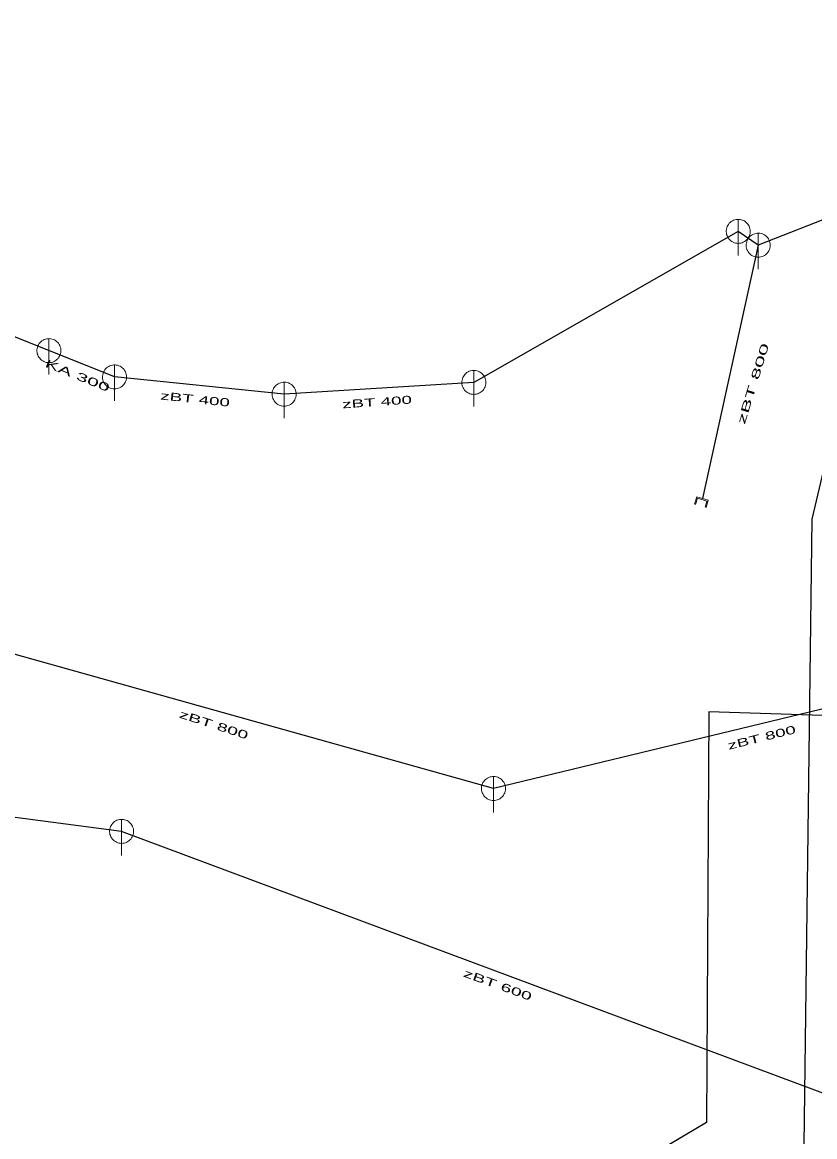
# Model space of a CAD drawing. Extents: x -688432 to -687974, y -973332 to -972704.
# Drawn here: x -688214.9 to -688148.9, y -972930.3 to -972837.5 of the extents above; entities that cross this region are included whole.
import ezdxf
from ezdxf.enums import TextEntityAlignment as Align

# ---------------------------------------------------------------- set-up
doc = ezdxf.new("R2010")
doc.units = 0
doc.header["$LTSCALE"] = 0.27
for name, color, linetype, lineweight in [('1', 7, 'Continuous', 25), ('14', 7, 'Continuous', 25), ('17', 7, 'Continuous', 25), ('22', 7, 'Continuous', 13), ('29', 7, 'Continuous', 13)]:
    doc.layers.add(name, color=color, linetype=linetype, lineweight=lineweight)

msp = doc.modelspace()

# ---------------------------------------------------------------- linework, layer by layer
at = {"layer": '1'}
msp.add_lwpolyline([(-688157.895, -972985.064), (-688131.748, -972983.489), (-688134.952, -972934.372), (-688122, -972934.52), (-688122.986, -972921.456), (-688135.938, -972921.308), (-688137.958, -972895.554), (-688157.714, -972894.909), (-688157.93, -972929.126), (-688173.215, -972938.189), (-688162.29, -972954.057)], close=True, dxfattribs=at)
at = {"layer": '14'}
for p, q in [((-688146.3, -972853.175), (-688153.616, -972856.054)), ((-688155.276, -972854.901), (-688177.28, -972867.48)), ((-688153.616, -972856.054), (-688155.276, -972854.901)), ((-688153.616, -972856.054), (-688158.259, -972877.162)), ((-688193.074, -972868.464), (-688207.188, -972867.028)), ((-688177.28, -972867.48), (-688193.074, -972868.464)), ((-688175.649, -972901.305), (-688217.084, -972889.702)), ((-688131.138, -972890.529), (-688175.649, -972901.305)), ((-688206.6, -972904.874), (-688245.539, -972899.801)), ((-688142.939, -972928.669), (-688206.6, -972904.874))]:
    msp.add_line(p, q, dxfattribs=at)
msp.add_lwpolyline([(-688207.188, -972867.028), (-688212.648, -972864.838), (-688224.272, -972860.177)], dxfattribs=at)
at = {"layer": '17'}
msp.add_lwpolyline([(-688123.609, -972815.609), (-688135.91, -972839.761), (-688146.524, -972867.704), (-688149.164, -972878.87), (-688150.368, -972974.473), (-688134.778, -973051.136), (-688125.903, -973068.701), (-688203.651, -973132.27), (-688148.612, -973199.748), (-688078.631, -973291.807), (-688049.631, -973331.642)], dxfattribs=at)
at = {"layer": '22'}
for p, q in [((-688155.276, -972856.901), (-688155.275, -972853.901)), ((-688153.616, -972858.054), (-688153.615, -972855.054)), ((-688212.648, -972866.838), (-688212.647, -972863.838)), ((-688207.188, -972869.028), (-688207.187, -972866.028)), ((-688177.28, -972869.48), (-688177.279, -972866.48)), ((-688193.074, -972870.464), (-688193.073, -972867.464)), ((-688175.65, -972903.305), (-688175.649, -972900.305)), ((-688206.6, -972906.874), (-688206.599, -972903.874))]:
    msp.add_line(p, q, dxfattribs=at)
for points in [[(-688154.276, -972854.901), (-688154.281, -972854.792), (-688154.299, -972854.684), (-688154.329, -972854.578), (-688154.369, -972854.477), (-688154.421, -972854.38), (-688154.483, -972854.29), (-688154.555, -972854.207), (-688154.635, -972854.133), (-688154.723, -972854.067), (-688154.817, -972854.012), (-688154.917, -972853.967), (-688155.022, -972853.934), (-688155.129, -972853.912), (-688155.238, -972853.902), (-688155.348, -972853.904), (-688155.456, -972853.918), (-688155.563, -972853.943), (-688155.666, -972853.98), (-688155.764, -972854.029), (-688155.856, -972854.087), (-688155.942, -972854.156), (-688156.019, -972854.233), (-688156.088, -972854.319), (-688156.147, -972854.411), (-688156.195, -972854.509), (-688156.232, -972854.612), (-688156.258, -972854.719), (-688156.272, -972854.827), (-688156.275, -972854.937), (-688156.265, -972855.046), (-688156.244, -972855.153), (-688156.21, -972855.257), (-688156.166, -972855.357), (-688156.111, -972855.452), (-688156.045, -972855.54), (-688155.971, -972855.62), (-688155.888, -972855.692), (-688155.798, -972855.754), (-688155.702, -972855.806), (-688155.6, -972855.847), (-688155.495, -972855.877), (-688155.387, -972855.895), (-688155.277, -972855.901), (-688155.168, -972855.895), (-688155.06, -972855.877), (-688154.955, -972855.848), (-688154.853, -972855.807), (-688154.756, -972855.755), (-688154.666, -972855.693), (-688154.583, -972855.622), (-688154.508, -972855.542), (-688154.443, -972855.454), (-688154.387, -972855.36), (-688154.343, -972855.26), (-688154.309, -972855.156), (-688154.287, -972855.048), (-688154.277, -972854.939)], [(-688152.616, -972856.054), (-688152.621, -972855.945), (-688152.639, -972855.837), (-688152.669, -972855.731), (-688152.709, -972855.63), (-688152.761, -972855.533), (-688152.823, -972855.443), (-688152.895, -972855.36), (-688152.975, -972855.286), (-688153.063, -972855.22), (-688153.157, -972855.165), (-688153.257, -972855.12), (-688153.362, -972855.087), (-688153.469, -972855.065), (-688153.578, -972855.055), (-688153.688, -972855.057), (-688153.796, -972855.071), (-688153.903, -972855.096), (-688154.006, -972855.133), (-688154.104, -972855.182), (-688154.196, -972855.24), (-688154.282, -972855.309), (-688154.359, -972855.386), (-688154.428, -972855.472), (-688154.487, -972855.564), (-688154.535, -972855.662), (-688154.572, -972855.765), (-688154.598, -972855.872), (-688154.612, -972855.98), (-688154.615, -972856.09), (-688154.605, -972856.199), (-688154.584, -972856.306), (-688154.55, -972856.41), (-688154.506, -972856.51), (-688154.451, -972856.605), (-688154.385, -972856.693), (-688154.311, -972856.773), (-688154.228, -972856.845), (-688154.138, -972856.907), (-688154.042, -972856.959), (-688153.94, -972857), (-688153.835, -972857.03), (-688153.727, -972857.048), (-688153.617, -972857.054), (-688153.508, -972857.048), (-688153.4, -972857.03), (-688153.295, -972857.001), (-688153.193, -972856.96), (-688153.096, -972856.908), (-688153.006, -972856.846), (-688152.923, -972856.775), (-688152.848, -972856.695), (-688152.783, -972856.607), (-688152.727, -972856.513), (-688152.683, -972856.413), (-688152.649, -972856.309), (-688152.627, -972856.201), (-688152.617, -972856.092)], [(-688211.648, -972864.838), (-688211.653, -972864.729), (-688211.671, -972864.621), (-688211.701, -972864.515), (-688211.741, -972864.414), (-688211.793, -972864.317), (-688211.855, -972864.227), (-688211.927, -972864.144), (-688212.007, -972864.07), (-688212.095, -972864.004), (-688212.189, -972863.949), (-688212.289, -972863.904), (-688212.394, -972863.871), (-688212.501, -972863.849), (-688212.61, -972863.839), (-688212.72, -972863.841), (-688212.828, -972863.855), (-688212.935, -972863.88), (-688213.038, -972863.917), (-688213.136, -972863.966), (-688213.228, -972864.024), (-688213.314, -972864.093), (-688213.391, -972864.17), (-688213.46, -972864.256), (-688213.519, -972864.348), (-688213.567, -972864.446), (-688213.604, -972864.549), (-688213.63, -972864.656), (-688213.644, -972864.764), (-688213.647, -972864.874), (-688213.637, -972864.983), (-688213.616, -972865.09), (-688213.582, -972865.194), (-688213.538, -972865.294), (-688213.483, -972865.389), (-688213.417, -972865.477), (-688213.343, -972865.557), (-688213.26, -972865.629), (-688213.17, -972865.691), (-688213.074, -972865.743), (-688212.972, -972865.784), (-688212.867, -972865.814), (-688212.759, -972865.832), (-688212.649, -972865.838), (-688212.54, -972865.832), (-688212.432, -972865.814), (-688212.327, -972865.785), (-688212.225, -972865.744), (-688212.128, -972865.692), (-688212.038, -972865.63), (-688211.955, -972865.559), (-688211.88, -972865.479), (-688211.815, -972865.391), (-688211.759, -972865.297), (-688211.715, -972865.197), (-688211.681, -972865.093), (-688211.659, -972864.985), (-688211.649, -972864.876)], [(-688206.188, -972867.028), (-688206.193, -972866.919), (-688206.211, -972866.811), (-688206.241, -972866.705), (-688206.281, -972866.604), (-688206.333, -972866.507), (-688206.395, -972866.417), (-688206.467, -972866.334), (-688206.547, -972866.26), (-688206.635, -972866.194), (-688206.729, -972866.139), (-688206.829, -972866.094), (-688206.934, -972866.061), (-688207.041, -972866.039), (-688207.15, -972866.029), (-688207.26, -972866.031), (-688207.368, -972866.045), (-688207.475, -972866.07), (-688207.578, -972866.107), (-688207.676, -972866.156), (-688207.768, -972866.214), (-688207.854, -972866.283), (-688207.931, -972866.36), (-688208, -972866.446), (-688208.059, -972866.538), (-688208.107, -972866.636), (-688208.144, -972866.739), (-688208.17, -972866.846), (-688208.184, -972866.954), (-688208.187, -972867.064), (-688208.177, -972867.173), (-688208.156, -972867.28), (-688208.122, -972867.384), (-688208.078, -972867.484), (-688208.023, -972867.579), (-688207.957, -972867.667), (-688207.883, -972867.747), (-688207.8, -972867.819), (-688207.71, -972867.881), (-688207.614, -972867.933), (-688207.512, -972867.974), (-688207.407, -972868.004), (-688207.299, -972868.022), (-688207.189, -972868.028), (-688207.08, -972868.022), (-688206.972, -972868.004), (-688206.867, -972867.975), (-688206.765, -972867.934), (-688206.668, -972867.882), (-688206.578, -972867.82), (-688206.495, -972867.749), (-688206.42, -972867.669), (-688206.355, -972867.581), (-688206.299, -972867.487), (-688206.255, -972867.387), (-688206.221, -972867.283), (-688206.199, -972867.175), (-688206.189, -972867.066)], [(-688176.28, -972867.48), (-688176.285, -972867.371), (-688176.303, -972867.263), (-688176.333, -972867.157), (-688176.373, -972867.056), (-688176.425, -972866.959), (-688176.487, -972866.869), (-688176.559, -972866.786), (-688176.639, -972866.712), (-688176.727, -972866.646), (-688176.821, -972866.591), (-688176.921, -972866.546), (-688177.026, -972866.513), (-688177.133, -972866.491), (-688177.242, -972866.481), (-688177.352, -972866.483), (-688177.46, -972866.497), (-688177.567, -972866.522), (-688177.67, -972866.559), (-688177.768, -972866.608), (-688177.86, -972866.666), (-688177.946, -972866.735), (-688178.023, -972866.812), (-688178.092, -972866.898), (-688178.151, -972866.99), (-688178.199, -972867.088), (-688178.236, -972867.191), (-688178.262, -972867.298), (-688178.276, -972867.406), (-688178.279, -972867.516), (-688178.269, -972867.625), (-688178.248, -972867.732), (-688178.214, -972867.836), (-688178.17, -972867.936), (-688178.115, -972868.031), (-688178.049, -972868.119), (-688177.975, -972868.199), (-688177.892, -972868.271), (-688177.802, -972868.333), (-688177.706, -972868.385), (-688177.604, -972868.426), (-688177.499, -972868.456), (-688177.391, -972868.474), (-688177.281, -972868.48), (-688177.172, -972868.474), (-688177.064, -972868.456), (-688176.959, -972868.427), (-688176.857, -972868.386), (-688176.76, -972868.334), (-688176.67, -972868.272), (-688176.587, -972868.201), (-688176.512, -972868.121), (-688176.447, -972868.033), (-688176.391, -972867.939), (-688176.347, -972867.839), (-688176.313, -972867.735), (-688176.291, -972867.627), (-688176.281, -972867.518)], [(-688192.074, -972868.464), (-688192.079, -972868.355), (-688192.097, -972868.247), (-688192.127, -972868.141), (-688192.167, -972868.04), (-688192.219, -972867.943), (-688192.281, -972867.853), (-688192.353, -972867.77), (-688192.433, -972867.696), (-688192.521, -972867.63), (-688192.615, -972867.575), (-688192.715, -972867.53), (-688192.82, -972867.497), (-688192.927, -972867.475), (-688193.036, -972867.465), (-688193.146, -972867.467), (-688193.254, -972867.481), (-688193.361, -972867.506), (-688193.464, -972867.543), (-688193.562, -972867.592), (-688193.654, -972867.65), (-688193.74, -972867.719), (-688193.817, -972867.796), (-688193.886, -972867.882), (-688193.945, -972867.974), (-688193.993, -972868.072), (-688194.03, -972868.175), (-688194.056, -972868.282), (-688194.07, -972868.39), (-688194.073, -972868.5), (-688194.063, -972868.609), (-688194.042, -972868.716), (-688194.008, -972868.82), (-688193.964, -972868.92), (-688193.909, -972869.015), (-688193.843, -972869.103), (-688193.769, -972869.183), (-688193.686, -972869.255), (-688193.596, -972869.317), (-688193.5, -972869.369), (-688193.398, -972869.41), (-688193.293, -972869.44), (-688193.185, -972869.458), (-688193.075, -972869.464), (-688192.966, -972869.458), (-688192.858, -972869.44), (-688192.753, -972869.411), (-688192.651, -972869.37), (-688192.554, -972869.318), (-688192.464, -972869.256), (-688192.381, -972869.185), (-688192.306, -972869.105), (-688192.241, -972869.017), (-688192.185, -972868.923), (-688192.141, -972868.823), (-688192.107, -972868.719), (-688192.085, -972868.611), (-688192.075, -972868.502)], [(-688174.65, -972901.305), (-688174.655, -972901.196), (-688174.673, -972901.088), (-688174.703, -972900.982), (-688174.743, -972900.881), (-688174.795, -972900.784), (-688174.857, -972900.694), (-688174.929, -972900.611), (-688175.009, -972900.537), (-688175.097, -972900.471), (-688175.191, -972900.416), (-688175.291, -972900.371), (-688175.396, -972900.338), (-688175.503, -972900.316), (-688175.612, -972900.306), (-688175.722, -972900.308), (-688175.83, -972900.322), (-688175.937, -972900.347), (-688176.04, -972900.384), (-688176.138, -972900.433), (-688176.23, -972900.491), (-688176.316, -972900.56), (-688176.393, -972900.637), (-688176.462, -972900.723), (-688176.521, -972900.815), (-688176.569, -972900.913), (-688176.606, -972901.016), (-688176.632, -972901.123), (-688176.646, -972901.231), (-688176.649, -972901.341), (-688176.639, -972901.45), (-688176.618, -972901.557), (-688176.584, -972901.661), (-688176.54, -972901.761), (-688176.485, -972901.856), (-688176.419, -972901.944), (-688176.345, -972902.024), (-688176.262, -972902.096), (-688176.172, -972902.158), (-688176.076, -972902.21), (-688175.974, -972902.251), (-688175.869, -972902.281), (-688175.761, -972902.299), (-688175.651, -972902.305), (-688175.542, -972902.299), (-688175.434, -972902.281), (-688175.329, -972902.252), (-688175.227, -972902.211), (-688175.13, -972902.159), (-688175.04, -972902.097), (-688174.957, -972902.026), (-688174.882, -972901.946), (-688174.817, -972901.858), (-688174.761, -972901.764), (-688174.717, -972901.664), (-688174.683, -972901.56), (-688174.661, -972901.452), (-688174.651, -972901.343)], [(-688205.6, -972904.874), (-688205.605, -972904.765), (-688205.623, -972904.657), (-688205.653, -972904.551), (-688205.693, -972904.45), (-688205.745, -972904.353), (-688205.807, -972904.263), (-688205.879, -972904.18), (-688205.959, -972904.106), (-688206.047, -972904.04), (-688206.141, -972903.985), (-688206.241, -972903.94), (-688206.346, -972903.907), (-688206.453, -972903.885), (-688206.562, -972903.875), (-688206.672, -972903.877), (-688206.78, -972903.891), (-688206.887, -972903.916), (-688206.99, -972903.953), (-688207.088, -972904.002), (-688207.18, -972904.06), (-688207.266, -972904.129), (-688207.343, -972904.206), (-688207.412, -972904.292), (-688207.471, -972904.384), (-688207.519, -972904.482), (-688207.556, -972904.585), (-688207.582, -972904.692), (-688207.596, -972904.8), (-688207.599, -972904.91), (-688207.589, -972905.019), (-688207.568, -972905.126), (-688207.534, -972905.23), (-688207.49, -972905.33), (-688207.435, -972905.425), (-688207.369, -972905.513), (-688207.295, -972905.593), (-688207.212, -972905.665), (-688207.122, -972905.727), (-688207.026, -972905.779), (-688206.924, -972905.82), (-688206.819, -972905.85), (-688206.711, -972905.868), (-688206.601, -972905.874), (-688206.492, -972905.868), (-688206.384, -972905.85), (-688206.279, -972905.821), (-688206.177, -972905.78), (-688206.08, -972905.728), (-688205.99, -972905.666), (-688205.907, -972905.595), (-688205.832, -972905.515), (-688205.767, -972905.427), (-688205.711, -972905.333), (-688205.667, -972905.233), (-688205.633, -972905.129), (-688205.611, -972905.021), (-688205.601, -972904.912)]]:
    msp.add_lwpolyline(points, close=True, dxfattribs=at)
at = {"layer": '29'}
for points in [[(-688157.957, -972877.898), (-688157.783, -972877.302), (-688158.734, -972877.022), (-688158.91, -972877.62)], [(-688158.826, -972877.644), (-688158.676, -972877.13), (-688157.891, -972877.361), (-688158.042, -972877.874)]]:
    msp.add_lwpolyline(points, dxfattribs=at)

# ---------------------------------------------------------------- texts
at = {"layer": '1'}
for s, rotation, width, p in [('zBT 800 ', 73, 2.1, (-688153.6453, -972867.4375)), ('zBT 800 ', 73, 2.1, (-688153.6453, -972867.4375)), ('zBT 800 ', 73, 2.1, (-688153.6453, -972867.4375)), ('zBT 800 ', 73, 2.1, (-688153.6453, -972867.4375)), ('zBT 800 ', 73, 2.1, (-688153.6453, -972867.4375)), ('KA 300', 338, 1.95, (-688210.3989, -972867.2224)), ('KA 300', 338, 1.95, (-688210.3989, -972867.2224)), ('KA 300', 338, 1.95, (-688210.3989, -972867.2224)), ('KA 300', 338, 1.95, (-688210.3989, -972867.2224)), ('KA 300', 338, 1.95, (-688210.3989, -972867.2224)), ('zBT 400 ', 354, 1.75, (-688200.2988, -972869.2256)), ('zBT 400 ', 354, 1.75, (-688200.2988, -972869.2256)), ('zBT 400 ', 354, 1.75, (-688200.2988, -972869.2256)), ('zBT 400 ', 354, 1.75, (-688200.2988, -972869.2256)), ('zBT 400 ', 354, 1.75, (-688200.2988, -972869.2256)), ('zBT 400 ', 4, 1.75, (-688185.1003, -972869.4289)), ('zBT 400 ', 4, 1.75, (-688185.1003, -972869.4289)), ('zBT 400 ', 4, 1.75, (-688185.1003, -972869.4289)), ('zBT 400 ', 4, 1.75, (-688185.1003, -972869.4289)), ('zBT 400 ', 4, 1.75, (-688185.1003, -972869.4289)), ('zBT 800 ', 342, 1.8, (-688198.818, -972896.3719)), ('zBT 800 ', 342, 1.8, (-688198.818, -972896.3719)), ('zBT 800 ', 342, 1.8, (-688198.818, -972896.3719)), ('zBT 800 ', 342, 1.8, (-688198.818, -972896.3719)), ('zBT 800 ', 342, 1.8, (-688198.818, -972896.3719)), ('zBT 800 ', 14, 1.75, (-688153.0346, -972897.3305)), ('zBT 800 ', 14, 1.75, (-688153.0346, -972897.3305)), ('zBT 800 ', 14, 1.75, (-688153.0346, -972897.3305)), ('zBT 800 ', 14, 1.75, (-688153.0346, -972897.3305)), ('zBT 800 ', 14, 1.75, (-688153.0346, -972897.3305)), ('zBT 600 ', 340, 1.8, (-688175.2, -972918.0468)), ('zBT 600 ', 340, 1.8, (-688175.2, -972918.0468)), ('zBT 600 ', 340, 1.8, (-688175.2, -972918.0468)), ('zBT 600 ', 340, 1.8, (-688175.2, -972918.0468)), ('zBT 600 ', 340, 1.8, (-688175.2, -972918.0468))]:
    msp.add_text(s, height=0.6667, rotation=rotation, dxfattribs=dict(at, width=width)).set_placement(p, align=Align.CENTER)

doc.saveas('drawing.dxf')
